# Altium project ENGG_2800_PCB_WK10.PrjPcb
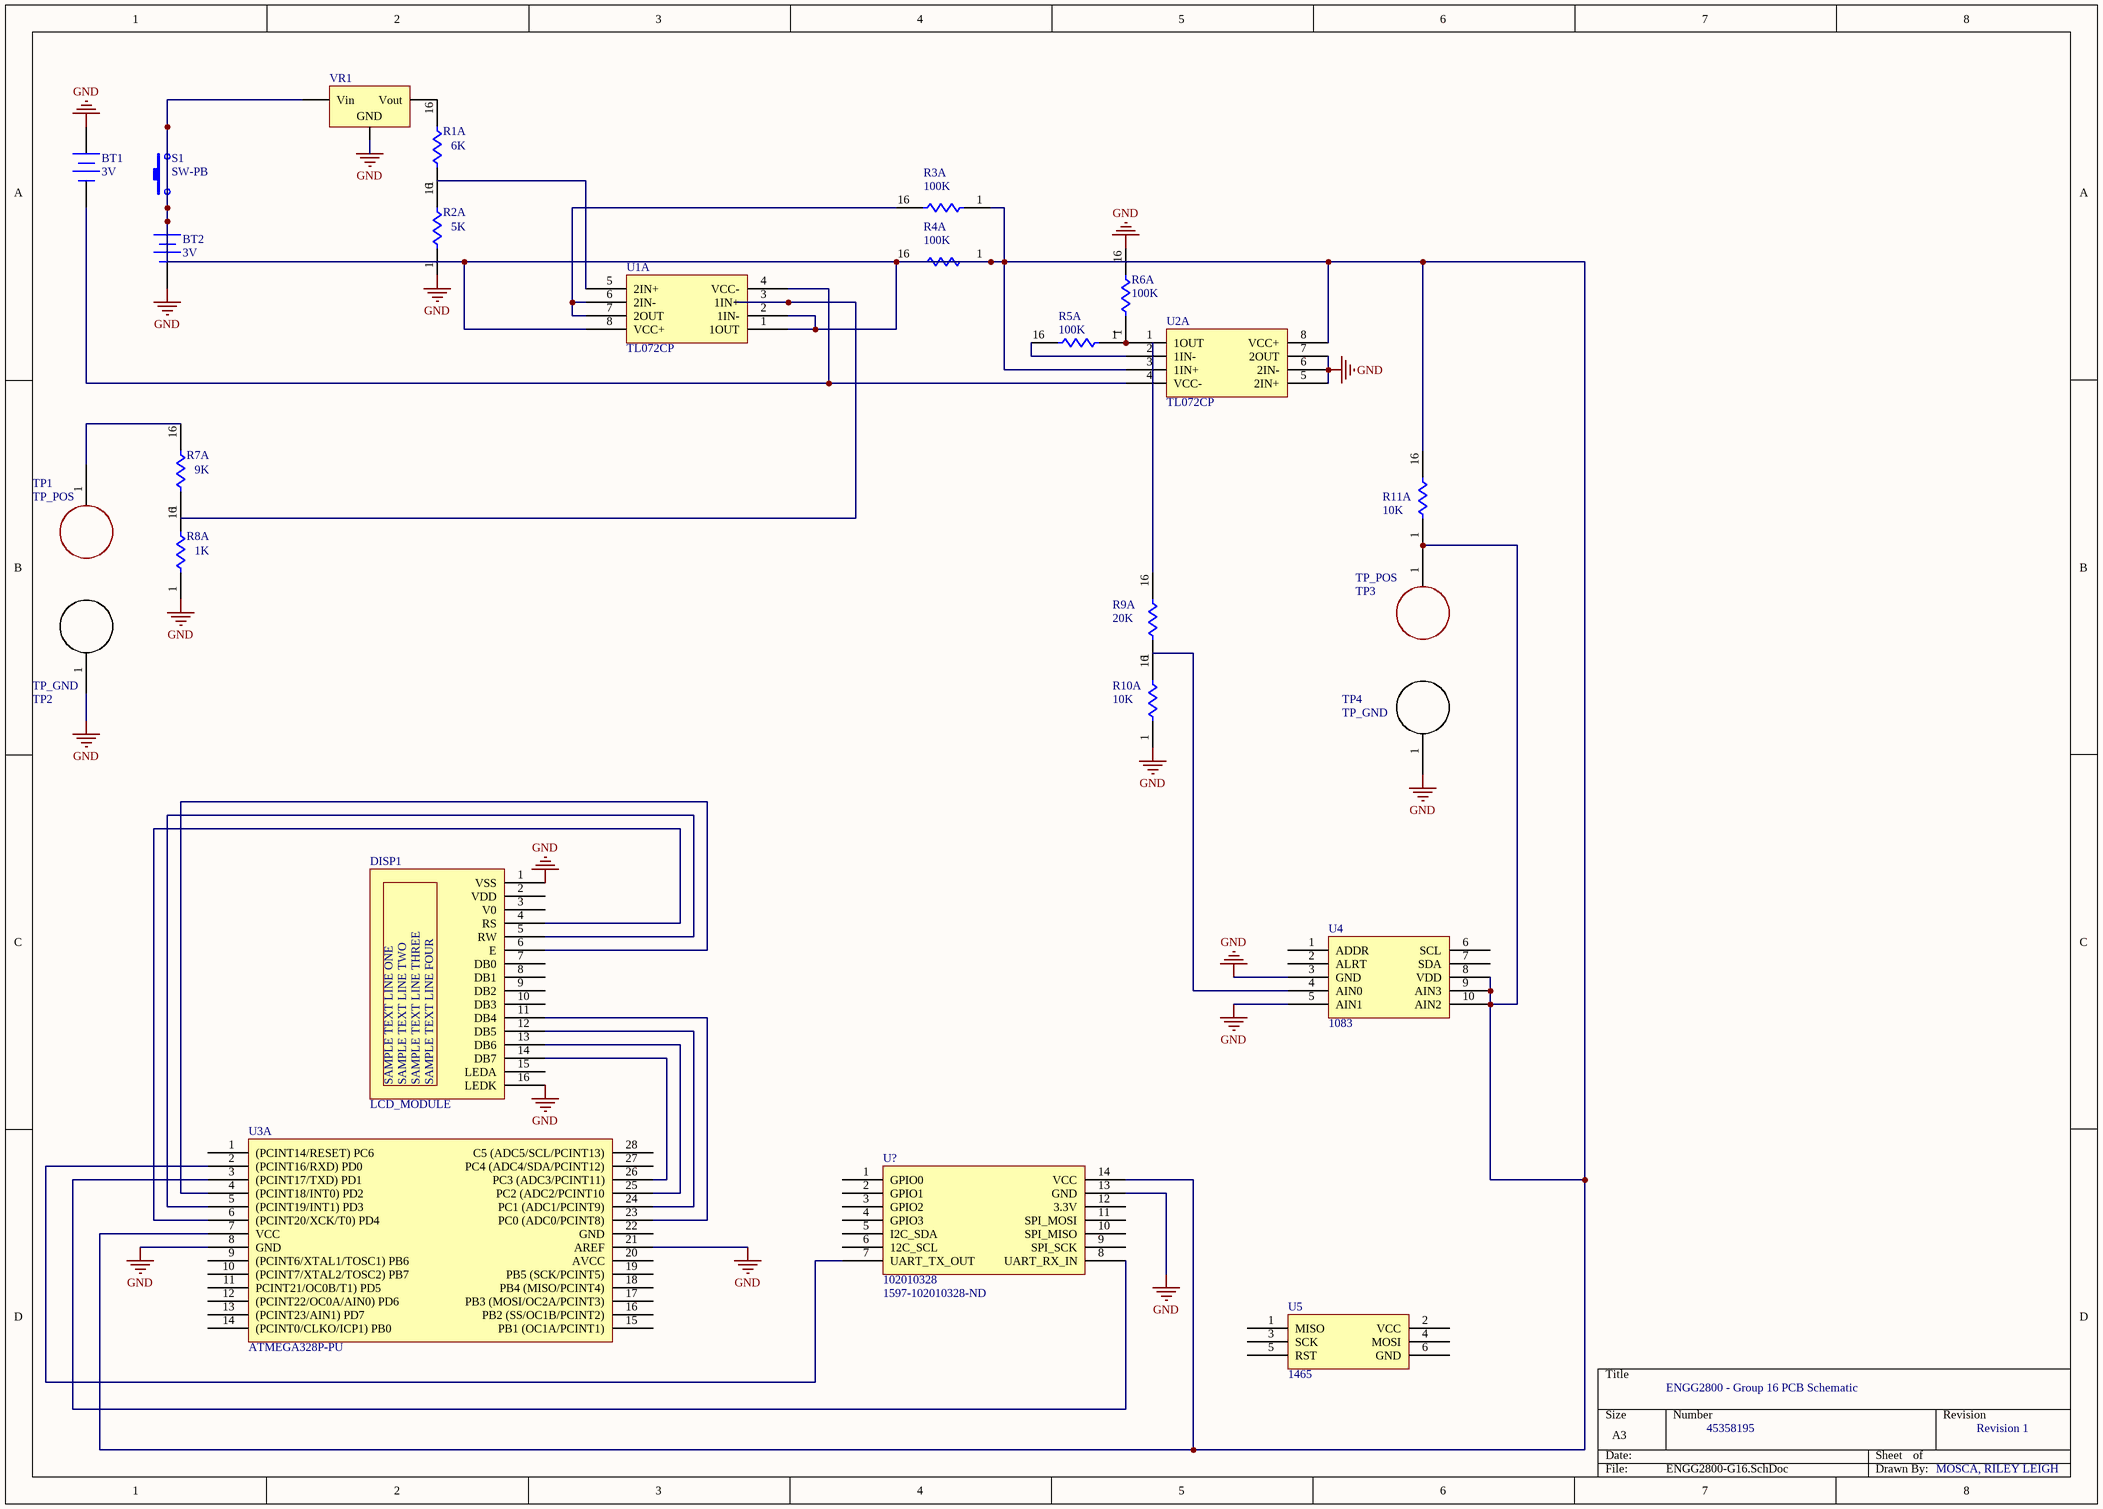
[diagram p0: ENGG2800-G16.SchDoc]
1 sheet, 26 parts. Net scope: global (net labels, ports and power ports of the same name join across sheets).

## Sheet ENGG2800-G16.SchDoc
size A3

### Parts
BT1  3V  [BAT-2]
BT2  3V  [BAT-2]
DISP1  LCD_MODULE
R1  value 6K  [SOIC16_N]  (hidden comment: Res Pack1)  (part A of 8)
R2  value 5K  [SOIC16_N]  (hidden comment: Res Pack1)  (part A of 8)
R3  value 100K  [SOIC16_N]  (hidden comment: Res Pack1)  (part A of 8)
R4  value 100K  [SOIC16_N]  (hidden comment: Res Pack1)  (part A of 8)
R5  value 100K  [SOIC16_N]  (hidden comment: Res Pack1)  (part A of 8)
R6  value 100K  [SOIC16_N]  (hidden comment: Res Pack1)  (part A of 8)
R7  value 9K  [SOIC16_N]  (hidden comment: Res Pack1)  (part A of 8)
R8  value 1K  [SOIC16_N]  (hidden comment: Res Pack1)  (part A of 8)
R9  value 20K  [SOIC16_N]  (hidden comment: Res Pack1)  (part A of 8)
R10  value 10K  [SOIC16_N]  (hidden comment: Res Pack1)  (part A of 8)
R11  value 10K  [SOIC16_N]  (hidden comment: Res Pack1)  (part A of 8)
S1  SW-PB  [SPST-2]
TP1  TP_POS
TP2  TP_GND
TP3  TP_POS
TP4  TP_GND
U1  TL072CP  (part A of 4)
U2  TL072CP  (part A of 4)
U3  ATMEGA328P-PU  (part A of 2)
U4  1083
U5  1465
U?  102010328  Supplier Part Number 1: 1597-102010328-ND
VR1  Volt Reg  [D2PAK_N]  (value not drawn)

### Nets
GND: BT1.1(+) BT2.2(-) DISP1.1(VSS) DISP1.16(LEDK) R2.1 R6.16 R8.1 R10.1 TP2.1 TP4.1 U2.5(2IN+) U2.6(2IN-) U2.7(2OUT) U3.8(GND) U3.21(AREF) U4.3(GND) U4.5(AIN1) U?.13(GND) VR1.2(GND)
NetBT1_2: BT1.2(-) U1.4(VCC-) U2.4(VCC-)
NetBT2_1: BT2.1(+) R3.1 R4.1 R4.16 R11.1 R11.16 S1.1 S1.2 TP3.1 U1.1(1OUT) U1.2(1IN-) U1.8(VCC+) U2.3(1IN+) U2.8(VCC+) U3.7(VCC) U4.8(VDD) U4.9(AIN3) U4.10(AIN2) U?.14(VCC) VR1.1(Vin)
NetDISP1_4: DISP1.4(RS) U3.6((PCINT20/XCK/T0)_PD4)
NetDISP1_5: DISP1.5(RW) U3.5((PCINT19/INT1)_PD3)
NetDISP1_6: DISP1.6(E) U3.4((PCINT18/INT0)_PD2)
NetDISP1_11: DISP1.11(DB4) U3.23(PC0_(ADC0/PCINT8))
NetDISP1_12: DISP1.12(DB5) U3.24(PC1_(ADC1/PCINT9))
NetDISP1_13: DISP1.13(DB6) U3.25(PC2_(ADC2/PCINT10)
NetDISP1_14: DISP1.14(DB7) U3.26(PC3_(ADC3/PCINT11))
NetR1_16: R1.16 VR1.3(Vout)
NetR2_16: R2.16 U1.5(2IN+)
NetR3_16: R3.16 U1.6(2IN-) U1.7(2OUT)
NetR5_1: R5.1 R6.1 U2.1(1OUT)
NetR5_16: R5.16 U2.2(1IN-)
NetR7_1: R7.1 U1.3(1IN+)
NetR7_16: R7.16 TP1.1
NetR10_16: R10.16 U4.4(AIN0)
NetU3_2: U3.2((PCINT16/RXD)_PD0) U?.7(UART_TX_OUT)
NetU3_3: U3.3((PCINT17/TXD)_PD1) U?.8(UART_RX_IN)

Not connected (* = marked no-connect by the designer): DISP1 2(VDD) 3(V0) 7(DB0) 8(DB1) 9(DB2) 10(DB3) 15(LEDA); R1 1; R8 16; R9 1 16; U3 1((PCINT14/RESET)_PC6) 9((PCINT6/XTAL1/TOSC1)_PB6) 10((PCINT7/XTAL2/TOSC2)_PB7) 11(PCINT21/OC0B/T1)_PD5) 12((PCINT22/OC0A/AIN0)_PD6) 13((PCINT23/AIN1)_PD7) 14((PCINT0/CLKO/ICP1)_PB0) 15(PB1_(OC1A/PCINT1)) 16(PB2_(SS/OC1B/PCINT2)) 17(PB3_(MOSI/OC2A/PCINT3)) 18(PB4_(MISO/PCINT4)) 19(PB5_(SCK/PCINT5)) 20(AVCC) 22(GND) 27(PC4_(ADC4/SDA/PCINT12)) 28(C5_(ADC5/SCL/PCINT13)); U4 1(ADDR) 2(ALRT) 6(SCL) 7(SDA); U5 1(MISO) 2(VCC) 3(SCK) 4(MOSI) 5(RST) 6(GND); U? 1(GPIO0) 2(GPIO1) 3(GPIO2) 4(GPIO3) 5(I2C_SDA) 6(12C_SCL) 9(SPI_SCK) 10(SPI_MISO) 11(SPI_MOSI) 12(3.3V)

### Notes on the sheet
- ENGG2800 - Group 16 PCB Schematic
- 45358195
- Revision 1
- MOSCA, RILEY LEIGH

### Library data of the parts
BT1 BT2 = Battery: Multicell Battery
R1-R11 = Res Pack1: Isolated Resistor Network - Parts; Sim Note: Enter the Resistance value into parameter field.
S1 = SW-PB: Switch
TP1 TP3 = TP_POS: Test Point MultiPurpose THM .445 L .125OD Heat Resistant Nylon 46 Red; Manufacturer: Keystone Electronics; Manufacturer Part Number: 5010; Body Material: Bronze,PBT; Plating: Silver; Number of Ports: 1; Inside Diameter: 1.78mm; Hole Diameter: 1.6mm
TP2 TP4 = TP_GND: Test Point MultiPurpose THM .445 L .125OD Heat Resistant Nylon 46 Red; Manufacturer: Keystone Electronics; Manufacturer Part Number: 5010; Body Material: Bronze,PBT; Plating: Silver; Number of Ports: 1; Inside Diameter: 1.78mm; Hole Diameter: 1.6mm
U1 U2 = TL072CP: IC, OP AMP, DUAL JFET, DIP8; Bandwidth:3MHz; No. of Amplifiers:2; Slew Rate:13V/ s; Supply Voltage Range:7V to 36V; Amplifier Case Style:DIP; No. of Pins:8; Operating Temperature Min:0 C; Operating Temperature Max:70 C; ;RoHS Compliant: Yes; Manufacturer: Texas Instruments; Bandwidth: 3MHz; Number of Channels: 2; Voltage Gain: 106.02dB; Nominal Supply Current: 5mA; Max Supply Voltage: 18V; Min Dual Supply Voltage: 3.5V; Dual Supply Voltage: 9V; Common Mode Rejection Ratio: 70dB; Slew Rate: 13V/µs; Max I/O Voltage: 10mV; Input Bias Current: 200pA; Input Offset Voltage (Vos): 3mV; Operating Supply Current: 1.4mA
U3 = ATMEGA328P-PU: IC MCU 8BIT 32KB FLASH 28DIP; Manufacturer: Microchip / Atmel; Core Architecture: AVR; RAM Size: 2KB; Number of PWM Channels: 6; Number of Timers/Counters: 3; Min Supply Voltage: 1.8V; Max Supply Voltage: 5.5V; Interface: I2C,SPI,UART,USART,2-Wire; Number of I/Os: 23; Frequency: 20MHz; Oscillator Type: Internal; Data Bus Width: 8b; Number of SPI Channels: 1; Watchdog Timer: Yes; Peripherals: Brown-out Detect/Reset,POR,PWM,WDT
U4 = 1083: EVAL BOARD ADS1115 16-BIT ADC; Manufacturer: Adafruit Industries; Number of Bits: 12; Evaluation Kit: Yes; Number of A/D Converters: 1; Sampling Rate: 3300S/s; Interface: I2C,Serial
U5 = 1465: Adafruit 6-pin AVR ISP Breadboard Adapter Mini Kit; Manufacturer: Adafruit Industries
U? = 102010328: Manufacturer: Seeed Studio
VR1 = Volt Reg: Voltage Regulator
